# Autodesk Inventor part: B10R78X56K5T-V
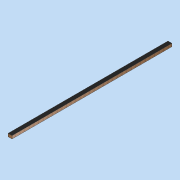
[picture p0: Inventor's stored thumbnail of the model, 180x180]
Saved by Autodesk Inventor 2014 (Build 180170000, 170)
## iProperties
Created: 2011-08
Part Number: B10R78X56K5T-V
Document SubType Name: Modeling
Designer: david.appleford
Density: 0.440547 g/cm^3
Description: Roof Edge Beam 2.5w - 5 Locks Ext 56mm + 68mm
Mass: 6000 g
Surface Area: 8443.6 cm^2
Volume: 13619.4 cm^3
Cost Center: £33.00
Material: 000 Redwood
Appearance: Wood (Oak)
Justset: False
Title: Roof Edge Beam 2.5w - 5 Locks
Author: david.appleford
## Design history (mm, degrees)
sketch "Sketch1"
  geometry: L1 (39, -34)-(-39, -34); L2 (-39, -34)-(-39, 3084); L3 (-39, 3084)-(39, 3084); L4 (39, 3084)-(39, -34); 1 further point
  constraints: 8 end point, 2 parallel, 1 horizontal, 1 perpendicular, 1 other
  dimensions: "d2" = 78 distance between parallel lines of L2 L4; "d3" = 34 distance from line of point (0, 0) L1; "d4" = 39 distance from line of point (0, 0) L2 (= 0.5 x d2); "d5" = 3118 distance of L3.end L1.start
extrude "Extrusion1" new body sketch "Sketch1" distance "d0" = 56; taper "d1" = 0 deg
body "Solid1"
